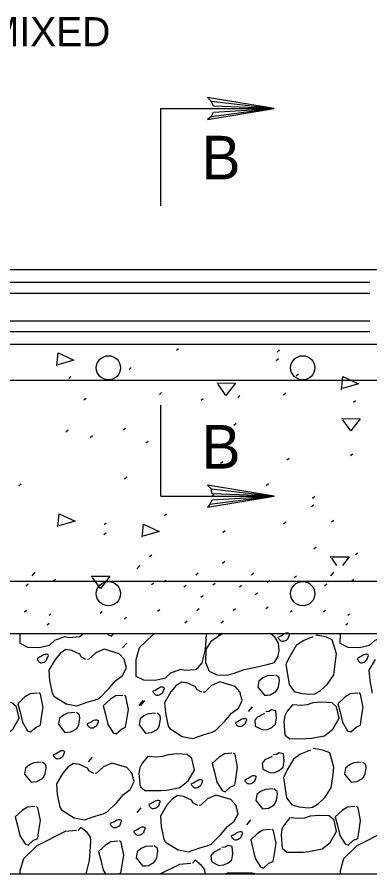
# Model space of a CAD drawing. Extents: x 3239 to 4230, y -4276 to -2494.
# Drawn here: x 3537.9 to 3574.2, y -3454.8 to -3366.5 of the extents above; entities that cross this region are included whole.
import ezdxf

# ---------------------------------------------------------------- set-up
doc = ezdxf.new("R2010")
doc.units = 0
doc.layers.add('2', color=7, linetype='Continuous')

msp = doc.modelspace()

# ---------------------------------------------------------------- linework, layer by layer
at = {"layer": '2'}
for p, q in [((3552.718, -3375.916), (3564.404, -3375.916)), ((3552.718, -3385.964), (3552.718, -3375.916)), ((3432.777, -3392.515), (3671.69, -3392.515)), ((3442.858, -3393.818), (3574.241, -3393.818)), ((3435.277, -3394.94), (3574.241, -3394.94)), ((3435.277, -3397.79), (3574.241, -3397.79)), ((3442.858, -3398.912), (3574.241, -3398.912)), ((3407.277, -3400.215), (3579.7, -3400.215)), ((3554.328, -3400.835), (3554.561, -3400.648)), ((3564.696, -3400.998), (3564.929, -3400.811)), ((3564.603, -3401.883), (3564.836, -3401.697)), ((3549.459, -3402.815), (3549.692, -3402.629)), ((3543.249, -3403.735), (3543.482, -3403.548)), ((3566.65, -3403.465), (3566.883, -3403.278)), ((3381.498, -3403.936), (3591.059, -3403.936)), ((3552.58, -3405.392), (3552.813, -3405.206)), ((3565.346, -3405.422), (3565.578, -3405.235)), ((3544.82, -3405.948), (3545.053, -3405.762)), ((3556.868, -3405.983), (3557.101, -3405.797)), ((3560.642, -3405.704), (3560.875, -3405.517)), ((3572.545, -3406.191), (3572.778, -3406.004)), ((3552.718, -3415.877), (3552.718, -3406.513)), ((3548.864, -3409.046), (3549.097, -3408.86)), ((3558.999, -3408.837), (3559.232, -3408.65)), ((3560.257, -3408.557), (3560.49, -3408.371)), ((3542.949, -3409.235), (3543.182, -3409.049)), ((3545.453, -3409.82), (3545.686, -3409.633)), ((3551.19, -3410.383), (3551.423, -3410.197)), ((3572.244, -3411.691), (3572.477, -3411.505)), ((3558.871, -3412.483), (3559.104, -3412.297)), ((3565.698, -3412.134), (3565.93, -3411.948)), ((3549.004, -3414.079), (3549.237, -3413.892)), ((3538.117, -3414.784), (3538.35, -3414.597)), ((3563.577, -3414.767), (3563.81, -3414.58)), ((3552.718, -3415.877), (3564.404, -3415.877)), ((3557.963, -3415.908), (3558.196, -3415.722)), ((3568.33, -3416.071), (3568.563, -3415.885)), ((3568.237, -3416.957), (3568.47, -3416.77)), ((3553.093, -3417.889), (3553.326, -3417.702)), ((3546.884, -3418.808), (3547.117, -3418.622)), ((3565.369, -3418.725), (3565.602, -3418.538)), ((3570.285, -3418.538), (3570.518, -3418.352)), ((3559.125, -3419.61), (3559.358, -3419.424)), ((3546.866, -3419.829), (3547.099, -3419.643)), ((3568.49, -3421.302), (3568.723, -3421.116)), ((3551.572, -3422.113), (3551.805, -3421.926)), ((3572.778, -3421.893), (3573.011, -3421.707)), ((3559.078, -3422.779), (3559.311, -3422.592)), ((3556.33, -3423.978), (3556.563, -3423.791)), ((3562.061, -3423.978), (3562.294, -3423.791)), ((3380.058, -3424.646), (3612.142, -3424.646)), ((3541.642, -3424.625), (3541.875, -3424.439)), ((3551.777, -3425.001), (3552.01, -3424.815)), ((3553.035, -3424.721), (3553.268, -3424.535)), ((3558.084, -3425.031), (3558.317, -3424.844)), ((3563.666, -3424.767), (3563.899, -3424.581)), ((3566.466, -3424.274), (3566.699, -3424.088)), ((3572.373, -3424.625), (3572.606, -3424.439)), ((3538.842, -3425.118), (3539.075, -3424.932)), ((3555.095, -3425.24), (3555.328, -3425.053)), ((3560.826, -3425.24), (3561.059, -3425.053)), ((3569.572, -3425.118), (3569.805, -3424.932)), ((3556.849, -3426.293), (3557.082, -3426.107)), ((3562.431, -3426.03), (3562.664, -3425.843)), ((3556.447, -3427.664), (3556.68, -3427.477)), ((3560.19, -3427.664), (3560.423, -3427.477)), ((3563.526, -3427.459), (3563.759, -3427.272)), ((3538.702, -3427.81), (3538.935, -3427.623)), ((3541.239, -3428.156), (3541.412, -3428.018)), ((3546.472, -3427.94), (3546.705, -3427.754)), ((3548.976, -3428.524), (3549.209, -3428.338)), ((3552.387, -3427.751), (3552.62, -3427.565)), ((3566.063, -3427.805), (3566.236, -3427.667)), ((3569.433, -3427.81), (3569.666, -3427.623)), ((3571.97, -3428.156), (3572.143, -3428.018)), ((3541.028, -3429.147), (3541.239, -3428.978)), ((3555.212, -3428.926), (3555.445, -3428.74)), ((3558.955, -3428.926), (3559.188, -3428.74)), ((3571.759, -3429.147), (3571.97, -3428.978)), ((3380.058, -3430.046), (3615.577, -3430.046)), ((3515.43, -3454.815), (3641.728, -3454.815))]:
    msp.add_line(p, q, dxfattribs=at)
for points in [[(3557.904, -3376.791), (3558.154, -3376.291), (3564.404, -3375.916), (3557.904, -3376.791), (3557.529, -3377.041), (3564.404, -3375.916), (3558.154, -3375.666), (3557.904, -3375.166), (3564.404, -3375.916), (3557.529, -3374.791), (3557.904, -3375.166)], [(3542.015, -3402.453), (3542.154, -3401.102), (3543.785, -3401.847), (3542.131, -3402.337)], [(3571.31, -3404.909), (3571.45, -3403.558), (3573.08, -3404.303), (3571.426, -3404.793)], [(3558.481, -3404.206), (3560.414, -3404.23), (3559.436, -3405.488), (3558.62, -3404.346)], [(3571.319, -3407.87), (3573.252, -3407.894), (3572.274, -3409.152), (3571.458, -3408.01)], [(3557.779, -3416.752), (3558.029, -3416.252), (3564.404, -3415.877), (3557.779, -3416.752), (3557.529, -3417.002), (3564.404, -3415.877), (3558.029, -3415.627), (3557.904, -3415.127), (3564.404, -3415.877), (3557.529, -3414.752), (3557.904, -3415.127)], [(3542.127, -3419.057), (3542.267, -3417.706), (3543.898, -3418.452), (3542.244, -3418.941)], [(3550.796, -3420.115), (3550.936, -3418.764), (3552.566, -3419.51), (3550.912, -3419.999)], [(3570.174, -3422.126), (3572.108, -3422.15), (3571.435, -3423.015)], [(3550.559, -3423.015), (3550.255, -3423.377)], [(3570.849, -3423.015), (3570.314, -3422.266)], [(3539.772, -3423.717), (3539.467, -3424.08)], [(3570.502, -3423.717), (3570.198, -3424.08)], [(3545.546, -3424.119), (3547.48, -3424.142), (3546.502, -3425.4), (3545.686, -3424.259)], [(3538.228, -3430.046), (3538.223, -3431.046), (3539.019, -3431.433), (3540.223, -3431.479), (3541.269, -3431.236), (3541.834, -3430.73), (3542.846, -3430.336), (3543.314, -3430.446), (3544.372, -3430.354), (3544.641, -3430.179), (3544.758, -3430.046)], [(3547.242, -3430.046), (3547.32, -3430.172), (3547.636, -3430.296), (3547.905, -3430.046)], [(3552.153, -3430.046), (3551.898, -3430.174), (3550.49, -3431.517), (3550.162, -3432.743), (3550.155, -3434.423), (3550.93, -3434.812), (3552.154, -3434.835), (3553.202, -3434.613), (3553.745, -3434.108), (3554.778, -3433.713), (3555.245, -3433.824), (3556.284, -3433.733), (3556.573, -3433.556), (3556.987, -3433.062), (3557.325, -3431.681), (3557.397, -3430.761), (3557.435, -3430.046)], [(3559.127, -3430.046), (3557.885, -3430.87), (3557.347, -3431.679), (3557.312, -3433.034), (3557.694, -3433.915), (3558.489, -3434.281), (3559.54, -3434.342), (3560.284, -3434.124), (3561.298, -3433.753), (3562.495, -3433.495), (3563.672, -3433.24), (3564.415, -3433.021), (3564.816, -3432.377), (3564.916, -3431.758), (3564.851, -3431.023), (3564.495, -3430.443), (3564.02, -3430.046)], [(3558.97, -3430.046), (3558.614, -3430.282)], [(3571.171, -3430.046), (3571.166, -3431.046), (3571.963, -3431.433), (3573.167, -3431.479), (3574.213, -3431.236), (3574.778, -3430.73), (3575.789, -3430.336), (3576.258, -3430.446), (3577.316, -3430.354), (3577.584, -3430.179), (3577.702, -3430.046)], [(3549.213, -3431.032), (3548.798, -3431.528)], [(3568.386, -3430.394), (3567.375, -3430.788), (3566.656, -3431.287), (3565.992, -3432.413), (3565.604, -3433.209), (3565.939, -3435.294), (3566.458, -3436.011), (3567.24, -3436.226), (3568.14, -3436.299), (3568.594, -3436.259), (3569.174, -3435.905), (3569.879, -3435.254), (3570.535, -3434.281), (3570.721, -3432.915), (3570.805, -3432.145), (3570.372, -3430.678), (3569.763, -3430.428), (3569.294, -3430.315), (3568.676, -3430.217)], [(3545.016, -3432.717), (3544.558, -3432.473), (3544.381, -3432.184), (3543.584, -3431.796), (3542.965, -3431.699), (3542.387, -3432.053), (3541.855, -3432.71), (3541.19, -3433.814), (3541.282, -3434.874), (3541.55, -3436.202), (3541.729, -3436.492), (3542.997, -3437.295), (3544.084, -3437.505), (3545.246, -3437.098), (3545.99, -3436.882), (3546.432, -3436.689), (3547.412, -3435.689), (3548.081, -3434.868), (3548.8, -3434.368), (3549.187, -3433.572), (3548.957, -3432.678), (3548.451, -3432.133), (3546.906, -3431.657), (3546.025, -3432.04), (3545.318, -3432.691), (3545.167, -3432.704)], [(3574.799, -3432.71), (3574.133, -3433.814), (3574.226, -3434.874), (3574.494, -3436.202)], [(3564.428, -3434.351), (3563.671, -3434.418), (3563.231, -3434.61), (3562.825, -3434.949), (3562.726, -3435.568), (3563.388, -3436.405), (3563.691, -3436.378), (3563.994, -3436.352), (3564.574, -3436.017), (3564.713, -3435.851), (3564.837, -3435.537), (3564.935, -3434.918), (3564.908, -3434.615), (3564.744, -3434.477), (3564.58, -3434.338)], [(3556.949, -3436.094), (3556.467, -3435.831), (3556.29, -3435.541), (3555.515, -3435.152), (3554.896, -3435.054), (3554.316, -3435.41), (3553.765, -3436.067), (3553.122, -3437.191), (3553.213, -3438.23), (3553.483, -3439.579), (3553.66, -3439.847), (3554.928, -3440.651), (3556.015, -3440.861), (3557.177, -3440.454), (3557.92, -3440.237), (3558.361, -3440.045), (3559.321, -3439.068), (3560.012, -3438.245), (3560.731, -3437.725), (3561.097, -3436.929), (3560.867, -3436.057), (3560.382, -3435.488), (3558.815, -3435.016), (3557.954, -3435.395), (3557.25, -3436.068), (3557.1, -3436.081)], [(3540.045, -3436.18), (3539.288, -3436.246), (3538.709, -3436.603), (3538.005, -3437.275), (3538.235, -3438.147), (3538.478, -3439.194), (3539.012, -3440.063), (3539.328, -3440.187), (3539.894, -3439.681), (3540.334, -3439.489), (3540.411, -3438.873), (3540.61, -3437.656), (3540.34, -3436.308), (3540.174, -3436.169)], [(3572.989, -3436.18), (3572.232, -3436.246), (3571.653, -3436.603), (3570.949, -3437.275), (3571.179, -3438.147), (3571.422, -3439.194), (3571.955, -3440.063), (3572.272, -3440.187), (3572.838, -3439.681), (3573.278, -3439.489), (3573.354, -3438.873), (3573.553, -3437.656), (3573.284, -3436.308), (3573.118, -3436.169)], [(3534.251, -3437.45), (3533.329, -3437.379), (3532.799, -3438.036), (3532.536, -3438.516), (3532.434, -3439.112), (3532.554, -3440.475), (3533.049, -3440.89), (3534.703, -3440.876), (3535.309, -3440.823), (3536.639, -3440.576), (3537.493, -3439.891), (3538.136, -3438.767), (3537.881, -3437.591), (3537.409, -3437.173), (3536.336, -3437.115), (3535.427, -3437.195), (3534.857, -3437.397), (3534.251, -3437.45)], [(3548.821, -3436.413), (3548.063, -3436.479), (3547.506, -3436.834), (3546.801, -3437.484), (3547.031, -3438.378), (3547.274, -3439.403), (3547.807, -3440.273), (3548.123, -3440.397), (3548.667, -3439.892), (3549.109, -3439.7), (3549.208, -3439.104), (3549.405, -3437.865), (3549.136, -3436.539), (3548.972, -3436.4)], [(3550.88, -3436.953), (3550.464, -3437.449)], [(3551.037, -3436.953), (3550.622, -3437.449)], [(3567.195, -3437.45), (3566.273, -3437.379), (3565.743, -3438.036), (3565.48, -3438.516), (3565.378, -3439.112), (3565.497, -3440.475), (3565.993, -3440.89), (3567.646, -3440.876), (3568.253, -3440.823), (3569.583, -3440.576), (3570.437, -3439.891), (3571.079, -3438.767), (3570.825, -3437.591), (3570.353, -3437.173), (3569.28, -3437.115), (3568.371, -3437.195), (3567.801, -3437.397), (3567.195, -3437.45)], [(3562.139, -3437.582), (3561.725, -3438.075)], [(3563.403, -3438.275), (3562.673, -3438.645), (3562.398, -3438.974), (3562.451, -3439.578), (3562.931, -3439.842), (3563.248, -3439.967), (3563.701, -3439.928), (3564.142, -3439.736), (3564.547, -3439.395), (3564.647, -3438.777), (3564.581, -3438.02), (3564.135, -3437.906), (3563.845, -3438.085), (3563.542, -3438.111)], [(3543.891, -3438.183), (3543.134, -3438.249), (3542.694, -3438.441), (3542.288, -3438.78), (3542.188, -3439.399), (3542.851, -3440.236), (3543.154, -3440.209), (3543.457, -3440.183), (3544.036, -3439.848), (3544.175, -3439.683), (3544.3, -3439.368), (3544.397, -3438.749), (3544.371, -3438.446), (3544.207, -3438.309), (3544.043, -3438.169)], [(3552.193, -3438.252), (3551.436, -3438.319), (3550.996, -3438.511), (3550.59, -3438.85), (3550.491, -3439.469), (3551.153, -3440.306), (3551.456, -3440.279), (3551.759, -3440.253), (3552.338, -3439.918), (3552.478, -3439.752), (3552.602, -3439.438), (3552.699, -3438.819), (3552.673, -3438.516), (3552.509, -3438.378), (3552.345, -3438.239)], [(3552.304, -3442.784), (3551.384, -3442.712), (3550.831, -3443.372), (3550.568, -3443.852), (3550.47, -3444.469), (3550.587, -3445.81), (3551.08, -3446.224), (3552.738, -3446.233), (3553.342, -3446.18), (3554.692, -3445.908), (3555.527, -3445.227), (3556.193, -3444.122), (3555.934, -3442.925), (3555.441, -3442.509), (3554.389, -3442.45), (3553.482, -3442.529), (3552.889, -3442.733), (3552.304, -3442.784)], [(3560.049, -3442.373), (3559.29, -3442.44), (3558.734, -3442.794), (3558.029, -3443.445), (3558.259, -3444.339), (3558.502, -3445.364), (3559.035, -3446.233), (3559.351, -3446.357), (3559.894, -3445.853), (3560.337, -3445.66), (3560.436, -3445.064), (3560.633, -3443.826), (3560.364, -3442.499), (3560.2, -3442.36)], [(3564.176, -3442.703), (3563.446, -3443.072), (3563.171, -3443.402), (3563.224, -3444.006), (3563.704, -3444.269), (3564.021, -3444.395), (3564.474, -3444.356), (3564.915, -3444.163), (3565.32, -3443.823), (3565.42, -3443.205), (3565.354, -3442.448), (3564.908, -3442.334), (3564.619, -3442.513), (3564.316, -3442.539)], [(3568.125, -3442.067), (3567.091, -3442.463), (3566.396, -3442.981), (3565.73, -3444.086), (3565.342, -3444.882), (3565.677, -3446.967), (3566.198, -3447.684), (3566.96, -3447.922), (3567.88, -3447.994), (3568.336, -3447.954), (3568.914, -3447.6), (3569.596, -3446.929), (3570.273, -3445.954), (3570.459, -3444.588), (3570.545, -3443.818), (3570.112, -3442.351), (3569.479, -3442.103), (3569.012, -3441.99), (3568.414, -3441.89)], [(3540.408, -3443.307), (3539.651, -3443.373), (3539.211, -3443.565), (3538.805, -3443.904), (3538.705, -3444.524), (3539.368, -3445.36), (3539.671, -3445.334), (3539.974, -3445.307), (3540.553, -3444.973), (3540.692, -3444.807), (3540.817, -3444.493), (3540.914, -3443.873), (3540.888, -3443.57), (3540.724, -3443.433), (3540.56, -3443.294)], [(3545.829, -3444.47), (3545.349, -3444.206), (3545.17, -3443.918), (3544.374, -3443.529), (3543.756, -3443.431), (3543.198, -3443.785), (3542.645, -3444.443), (3541.979, -3445.547), (3542.072, -3446.607), (3542.343, -3447.956), (3542.519, -3448.225), (3543.808, -3449.026), (3544.873, -3449.238), (3546.059, -3448.829), (3546.781, -3448.614), (3547.221, -3448.424), (3548.203, -3447.444), (3548.872, -3446.623), (3549.589, -3446.103), (3549.977, -3445.306), (3549.749, -3444.432), (3549.242, -3443.866), (3547.697, -3443.392), (3546.815, -3443.774), (3546.111, -3444.445), (3545.982, -3444.456)], [(3545.661, -3442.774), (3545.245, -3443.27)], [(3573.351, -3443.307), (3572.595, -3443.373), (3572.154, -3443.565), (3571.748, -3443.904), (3571.649, -3444.524), (3572.311, -3445.36), (3572.614, -3445.334), (3572.917, -3445.307), (3573.497, -3444.973), (3573.636, -3444.807), (3573.76, -3444.493), (3573.858, -3443.873), (3573.832, -3443.57), (3573.668, -3443.433), (3573.504, -3443.294)], [(3564.246, -3446.046), (3563.49, -3446.112), (3563.047, -3446.304), (3562.618, -3446.624), (3562.521, -3447.243), (3563.204, -3448.099), (3563.508, -3448.073), (3563.811, -3448.046), (3564.39, -3447.69), (3564.506, -3447.526), (3564.632, -3447.21), (3564.73, -3446.593), (3564.705, -3446.311), (3564.541, -3446.174), (3564.375, -3446.035)], [(3556.53, -3447.767), (3556.05, -3447.504), (3555.871, -3447.214), (3555.076, -3446.848), (3554.459, -3446.75), (3553.901, -3447.105), (3553.345, -3447.74), (3552.682, -3448.866), (3552.774, -3449.926), (3553.044, -3451.254), (3553.221, -3451.544), (3554.509, -3452.324), (3555.574, -3452.536), (3556.759, -3452.127), (3557.483, -3451.933), (3557.924, -3451.741), (3558.904, -3450.741), (3559.594, -3449.918), (3560.29, -3449.399), (3560.679, -3448.624), (3560.449, -3447.73), (3559.942, -3447.163), (3558.398, -3446.711), (3557.515, -3447.07), (3556.833, -3447.741), (3556.68, -3447.754)], [(3539.765, -3447.877), (3539.007, -3447.943), (3538.451, -3448.297), (3537.745, -3448.948), (3537.975, -3449.842), (3538.218, -3450.867), (3538.751, -3451.736), (3539.068, -3451.86), (3539.611, -3451.356), (3540.053, -3451.163), (3540.153, -3450.567), (3540.349, -3449.329), (3540.08, -3448.003), (3539.916, -3447.863)], [(3550.671, -3447.999), (3550.255, -3448.494)], [(3572.709, -3447.877), (3571.951, -3447.943), (3571.394, -3448.297), (3570.689, -3448.948), (3570.919, -3449.842), (3571.162, -3450.867), (3571.695, -3451.736), (3572.011, -3451.86), (3572.554, -3451.356), (3572.997, -3451.163), (3573.096, -3450.567), (3573.293, -3449.329), (3573.024, -3448.003), (3572.86, -3447.863)], [(3561.956, -3449.253), (3561.54, -3449.748)], [(3566.933, -3449.123), (3566.013, -3449.051), (3565.46, -3449.711), (3565.196, -3450.191), (3565.098, -3450.808), (3565.216, -3452.15), (3565.709, -3452.564), (3567.367, -3452.572), (3567.971, -3452.519), (3569.321, -3452.248), (3570.155, -3451.566), (3570.821, -3450.461), (3570.563, -3449.264), (3570.069, -3448.848), (3569.018, -3448.789), (3568.111, -3448.868), (3567.518, -3449.072), (3566.933, -3449.123)], [(3544.057, -3450.356), (3542.868, -3450.46), (3539.967, -3451.933), (3538.581, -3453.276), (3538.231, -3454.505), (3538.23, -3454.815)], [(3545.059, -3454.815), (3545.393, -3453.421), (3545.466, -3452.52), (3545.525, -3451.447), (3545.486, -3450.993), (3545.143, -3450.566), (3544.486, -3450.035), (3544.207, -3450.343)], [(3564.002, -3450.245), (3563.243, -3450.311), (3562.687, -3450.665), (3561.981, -3451.316), (3562.211, -3452.21), (3562.454, -3453.235), (3562.988, -3454.105), (3563.304, -3454.229), (3563.847, -3453.724), (3564.289, -3453.532), (3564.389, -3452.936), (3564.586, -3451.697), (3564.316, -3450.371), (3564.152, -3450.232)], [(3577, -3450.356), (3575.812, -3450.46), (3572.91, -3451.933), (3571.525, -3453.276), (3571.175, -3454.505), (3571.173, -3454.815)], [(3548.333, -3451.429), (3547.575, -3451.496), (3547.019, -3451.85), (3546.313, -3452.5), (3546.543, -3453.395), (3546.786, -3454.419), (3547.029, -3454.815)], [(3548.394, -3454.815), (3548.621, -3454.716), (3548.721, -3454.12), (3548.918, -3452.881), (3548.648, -3451.555), (3548.484, -3451.416)], [(3551.896, -3451.945), (3551.139, -3452.011), (3550.699, -3452.203), (3550.293, -3452.542), (3550.194, -3453.162), (3550.856, -3453.998), (3551.159, -3453.972), (3551.462, -3453.945), (3552.042, -3453.611), (3552.181, -3453.445), (3552.305, -3453.131), (3552.403, -3452.511), (3552.376, -3452.208), (3552.212, -3452.071), (3552.048, -3451.932)], [(3558.882, -3452.247), (3558.152, -3452.616), (3557.877, -3452.945), (3557.93, -3453.549), (3558.41, -3453.813), (3558.727, -3453.939), (3559.18, -3453.899), (3559.621, -3453.707), (3560.026, -3453.366), (3560.126, -3452.748), (3560.06, -3451.992), (3559.614, -3451.877), (3559.324, -3452.056), (3559.021, -3452.083)], [(3555.832, -3453.733), (3554.641, -3453.837), (3552.69, -3454.815)], [(3557.297, -3454.815), (3557.297, -3454.805), (3557.259, -3454.371), (3556.918, -3453.943), (3556.259, -3453.39), (3555.983, -3453.72)], [(3561.844, -3454.71), (3559.582, -3454.756), (3559.494, -3454.815)], [(3562.407, -3454.815), (3561.995, -3454.697), (3561.912, -3454.815)]]:
    msp.add_lwpolyline(points, dxfattribs=at)
for centre in [(3547.337, -3402.653), (3567.337, -3402.653), (3547.337, -3425.929), (3567.337, -3425.929)]:
    msp.add_circle(centre, 1.247, dxfattribs=at)
for points in [[(3565.857, -3430.377), (3565.788, -3430.578), (3565.627, -3430.746), (3565.201, -3430.848), (3564.945, -3430.674), (3564.836, -3430.421), (3565.107, -3430.268), (3565.626, -3429.982), (3565.936, -3430.043), (3565.837, -3430.401)], [(3541.039, -3432.586), (3540.968, -3432.788), (3540.807, -3432.932), (3540.383, -3433.057), (3540.127, -3432.883), (3540.04, -3432.628), (3540.308, -3432.453), (3540.807, -3432.191), (3541.139, -3432.25), (3541.039, -3432.586)], [(3573.983, -3432.586), (3573.912, -3432.788), (3573.751, -3432.932), (3573.326, -3433.057), (3573.071, -3432.883), (3572.983, -3432.628), (3573.252, -3432.453), (3573.751, -3432.191), (3574.083, -3432.25), (3573.983, -3432.586)], [(3552.97, -3435.942), (3552.899, -3436.143), (3552.738, -3436.289), (3552.313, -3436.413), (3552.058, -3436.238), (3551.949, -3435.988), (3552.219, -3435.832), (3552.738, -3435.548), (3553.049, -3435.608), (3552.971, -3435.963)], [(3546.196, -3439.328), (3546.125, -3439.529), (3545.965, -3439.675), (3545.54, -3439.799), (3545.285, -3439.624), (3545.176, -3439.374), (3545.446, -3439.218), (3545.965, -3438.932), (3546.276, -3438.994), (3546.177, -3439.351)], [(3561.444, -3439.166), (3561.375, -3439.367), (3561.214, -3439.535), (3560.788, -3439.637), (3560.536, -3439.484), (3560.447, -3439.232), (3560.715, -3439.055), (3561.216, -3438.794), (3561.523, -3438.832), (3561.446, -3439.188)], [(3542.713, -3442.502), (3542.642, -3442.703), (3542.482, -3442.849), (3542.057, -3442.973), (3541.802, -3442.798), (3541.693, -3442.547), (3541.963, -3442.392), (3542.482, -3442.106), (3542.793, -3442.168), (3542.694, -3442.525)], [(3556.919, -3445.497), (3556.848, -3445.698), (3556.687, -3445.844), (3556.262, -3445.968), (3556.007, -3445.794), (3555.898, -3445.543), (3556.168, -3445.387), (3556.687, -3445.102), (3556.998, -3445.163), (3556.899, -3445.52)], [(3562.422, -3445.079), (3562.351, -3445.28), (3562.19, -3445.426), (3561.765, -3445.55), (3561.51, -3445.376), (3561.401, -3445.125), (3561.671, -3444.969), (3562.19, -3444.684), (3562.501, -3444.745), (3562.402, -3445.102)], [(3552.55, -3447.615), (3552.483, -3447.837), (3552.321, -3447.984), (3551.874, -3448.109), (3551.642, -3447.933), (3551.532, -3447.682), (3551.8, -3447.505), (3552.323, -3447.243), (3552.63, -3447.281), (3552.531, -3447.638)], [(3548.565, -3449.607), (3548.494, -3449.808), (3548.333, -3449.954), (3547.909, -3450.078), (3547.653, -3449.903), (3547.544, -3449.653), (3547.814, -3449.497), (3548.333, -3449.212), (3548.644, -3449.273), (3548.545, -3449.63)], [(3550.997, -3450.373), (3550.927, -3450.575), (3550.766, -3450.72), (3550.341, -3450.844), (3550.086, -3450.67), (3549.977, -3450.419), (3550.247, -3450.264), (3550.766, -3449.978), (3551.077, -3450.039), (3550.978, -3450.397)], [(3561.028, -3450.861), (3560.958, -3451.062), (3560.797, -3451.208), (3560.372, -3451.332), (3560.117, -3451.157), (3560.008, -3450.907), (3560.278, -3450.751), (3560.797, -3450.465), (3561.108, -3450.527), (3561.009, -3450.884)]]:
    msp.add_spline(points, degree=3, dxfattribs=at)

# ---------------------------------------------------------------- texts
for s, height, p in [('FILL KERF WITH PREMIXED', 3, (3494.258, -3369.5)), ('B', 4.5, (3556.922, -3383.233)), ('B', 4.5, (3556.922, -3413.045))]:
    msp.add_text(s, height=height, dxfattribs=at).set_placement(p)

doc.saveas('drawing.dxf')
